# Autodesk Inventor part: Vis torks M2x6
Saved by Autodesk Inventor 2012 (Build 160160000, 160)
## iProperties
Created: 2012-11
Part Number: Vis torks M2x6
Material: Default
Document SubType Name: Modeling
Designer: Administrateur
Density: 1 g/cm^3
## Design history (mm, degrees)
node "Vis torks M2x61"
node "Vis torks M2x6"
node "Base1"
